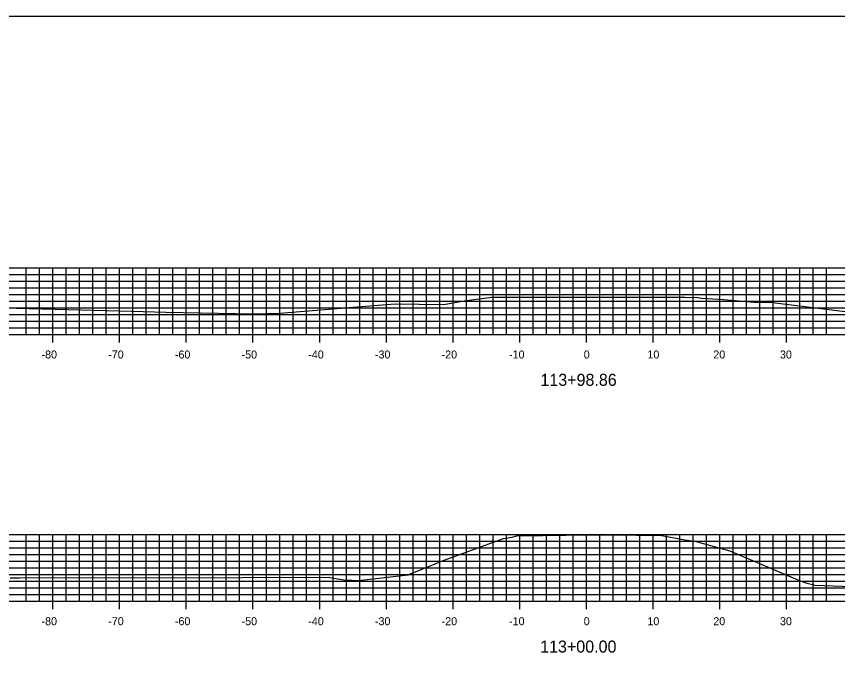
# Model space of a CAD drawing. Extents: x 1661012 to 1662122, y 670053 to 671852.
# Drawn here: x 1661506.5 to 1661629.7, y 671369.5 to 671466.8 of the extents above; entities that cross this region are included whole.
import ezdxf

# ---------------------------------------------------------------- set-up
doc = ezdxf.new("R2010")
doc.units = 0
for name, color, linetype in [('R_Concrete', 7, 'Continuous'), ('R_Concrete Hidden', 7, 'Continuous'), ('R_Erosion', 7, 'Continuous'), ('R_Exist Surface', 7, 'Continuous'), ('R_Proposed Road', 7, 'Continuous')]:
    doc.layers.add(name, color=color, linetype=linetype)

msp = doc.modelspace()

# ---------------------------------------------------------------- linework, layer by layer
at = {"layer": 'R_Concrete'}
for p, q in [((1661441.99, 671429.12), (1661741.99, 671429.12)), ((1661507.99, 671419.12), (1661507.99, 671429.12)), ((1661509.99, 671419.12), (1661509.99, 671429.12)), ((1661511.99, 671419.12), (1661511.99, 671429.12)), ((1661513.99, 671419.12), (1661513.99, 671429.12)), ((1661515.99, 671419.12), (1661515.99, 671429.12)), ((1661517.99, 671419.12), (1661517.99, 671429.12)), ((1661519.99, 671419.12), (1661519.99, 671429.12)), ((1661521.99, 671419.12), (1661521.99, 671429.12)), ((1661523.99, 671419.12), (1661523.99, 671429.12)), ((1661525.99, 671419.12), (1661525.99, 671429.12)), ((1661527.99, 671419.12), (1661527.99, 671429.12)), ((1661529.99, 671419.12), (1661529.99, 671429.12)), ((1661531.99, 671419.12), (1661531.99, 671429.12)), ((1661533.99, 671419.12), (1661533.99, 671429.12)), ((1661535.99, 671419.12), (1661535.99, 671429.12)), ((1661537.99, 671419.12), (1661537.99, 671429.12)), ((1661539.99, 671419.12), (1661539.99, 671429.12)), ((1661541.99, 671419.12), (1661541.99, 671429.12)), ((1661543.99, 671419.12), (1661543.99, 671429.12)), ((1661545.99, 671419.12), (1661545.99, 671429.12)), ((1661547.99, 671419.12), (1661547.99, 671429.12)), ((1661549.99, 671419.12), (1661549.99, 671429.12)), ((1661551.99, 671419.12), (1661551.99, 671429.12)), ((1661553.99, 671419.12), (1661553.99, 671429.12)), ((1661555.99, 671419.12), (1661555.99, 671429.12)), ((1661557.99, 671419.12), (1661557.99, 671429.12)), ((1661559.99, 671419.12), (1661559.99, 671429.12)), ((1661561.99, 671419.12), (1661561.99, 671429.12)), ((1661563.99, 671419.12), (1661563.99, 671429.12)), ((1661565.99, 671419.12), (1661565.99, 671429.12)), ((1661567.99, 671419.12), (1661567.99, 671429.12)), ((1661569.99, 671419.12), (1661569.99, 671429.12)), ((1661571.99, 671419.12), (1661571.99, 671429.12)), ((1661573.99, 671419.12), (1661573.99, 671429.12)), ((1661575.99, 671419.12), (1661575.99, 671429.12)), ((1661577.99, 671419.12), (1661577.99, 671429.12)), ((1661579.99, 671419.12), (1661579.99, 671429.12)), ((1661581.99, 671419.12), (1661581.99, 671429.12)), ((1661583.99, 671419.12), (1661583.99, 671429.12)), ((1661585.99, 671419.12), (1661585.99, 671429.12)), ((1661587.99, 671419.12), (1661587.99, 671429.12)), ((1661589.99, 671419.12), (1661589.99, 671429.12)), ((1661591.99, 671419.12), (1661591.99, 671429.12)), ((1661593.99, 671419.12), (1661593.99, 671429.12)), ((1661595.99, 671419.12), (1661595.99, 671429.12)), ((1661597.99, 671419.12), (1661597.99, 671429.12)), ((1661599.99, 671419.12), (1661599.99, 671429.12)), ((1661601.99, 671419.12), (1661601.99, 671429.12)), ((1661603.99, 671419.12), (1661603.99, 671429.12)), ((1661605.99, 671419.12), (1661605.99, 671429.12)), ((1661607.99, 671419.12), (1661607.99, 671429.12)), ((1661609.99, 671419.12), (1661609.99, 671429.12)), ((1661611.99, 671419.12), (1661611.99, 671429.12)), ((1661613.99, 671419.12), (1661613.99, 671429.12)), ((1661615.99, 671419.12), (1661615.99, 671429.12)), ((1661617.99, 671419.12), (1661617.99, 671429.12)), ((1661619.99, 671419.12), (1661619.99, 671429.12)), ((1661621.99, 671419.12), (1661621.99, 671429.12)), ((1661623.99, 671419.12), (1661623.99, 671429.12)), ((1661625.99, 671419.12), (1661625.99, 671429.12)), ((1661627.99, 671419.12), (1661627.99, 671429.12)), ((1661441.99, 671428.12), (1661741.99, 671428.12)), ((1661441.99, 671427.12), (1661741.99, 671427.12)), ((1661441.99, 671426.12), (1661741.99, 671426.12)), ((1661441.99, 671425.12), (1661741.99, 671425.12)), ((1661441.99, 671424.12), (1661741.99, 671424.12)), ((1661441.99, 671423.12), (1661741.99, 671423.12)), ((1661441.99, 671422.12), (1661741.99, 671422.12)), ((1661441.99, 671421.12), (1661741.99, 671421.12)), ((1661441.99, 671420.12), (1661741.99, 671420.12)), ((1661507.99, 671419.12), (1661507.99, 671419.72)), ((1661509.99, 671419.12), (1661509.99, 671419.72)), ((1661511.99, 671417.92), (1661511.99, 671420.32)), ((1661513.99, 671419.12), (1661513.99, 671419.72)), ((1661515.99, 671419.12), (1661515.99, 671419.72)), ((1661517.99, 671419.12), (1661517.99, 671419.72)), ((1661519.99, 671419.12), (1661519.99, 671419.72)), ((1661521.99, 671417.92), (1661521.99, 671420.32)), ((1661523.99, 671419.12), (1661523.99, 671419.72)), ((1661525.99, 671419.12), (1661525.99, 671419.72)), ((1661527.99, 671419.12), (1661527.99, 671419.72)), ((1661529.99, 671419.12), (1661529.99, 671419.72)), ((1661531.99, 671417.92), (1661531.99, 671420.32)), ((1661533.99, 671419.12), (1661533.99, 671419.72)), ((1661535.99, 671419.12), (1661535.99, 671419.72)), ((1661537.99, 671419.12), (1661537.99, 671419.72)), ((1661539.99, 671419.12), (1661539.99, 671419.72)), ((1661541.99, 671417.92), (1661541.99, 671420.32)), ((1661543.99, 671419.12), (1661543.99, 671419.72)), ((1661545.99, 671419.12), (1661545.99, 671419.72)), ((1661547.99, 671419.12), (1661547.99, 671419.72)), ((1661549.99, 671419.12), (1661549.99, 671419.72)), ((1661551.99, 671417.92), (1661551.99, 671420.32)), ((1661553.99, 671419.12), (1661553.99, 671419.72)), ((1661555.99, 671419.12), (1661555.99, 671419.72)), ((1661557.99, 671419.12), (1661557.99, 671419.72)), ((1661559.99, 671419.12), (1661559.99, 671419.72)), ((1661561.99, 671417.92), (1661561.99, 671420.32)), ((1661563.99, 671419.12), (1661563.99, 671419.72)), ((1661565.99, 671419.12), (1661565.99, 671419.72)), ((1661567.99, 671419.12), (1661567.99, 671419.72)), ((1661569.99, 671419.12), (1661569.99, 671419.72)), ((1661571.99, 671417.92), (1661571.99, 671420.32)), ((1661573.99, 671419.12), (1661573.99, 671419.72)), ((1661575.99, 671419.12), (1661575.99, 671419.72)), ((1661577.99, 671419.12), (1661577.99, 671419.72)), ((1661579.99, 671419.12), (1661579.99, 671419.72)), ((1661581.99, 671417.92), (1661581.99, 671420.32)), ((1661583.99, 671419.12), (1661583.99, 671419.72)), ((1661585.99, 671419.12), (1661585.99, 671419.72)), ((1661587.99, 671419.12), (1661587.99, 671419.72)), ((1661589.99, 671419.12), (1661589.99, 671419.72)), ((1661591.99, 671417.92), (1661591.99, 671420.32)), ((1661593.99, 671419.12), (1661593.99, 671419.72)), ((1661595.99, 671419.12), (1661595.99, 671419.72)), ((1661597.99, 671419.12), (1661597.99, 671419.72)), ((1661599.99, 671419.12), (1661599.99, 671419.72)), ((1661601.99, 671417.92), (1661601.99, 671420.32)), ((1661603.99, 671419.12), (1661603.99, 671419.72)), ((1661605.99, 671419.12), (1661605.99, 671419.72)), ((1661607.99, 671419.12), (1661607.99, 671419.72)), ((1661609.99, 671419.12), (1661609.99, 671419.72)), ((1661611.99, 671417.92), (1661611.99, 671420.32)), ((1661613.99, 671419.12), (1661613.99, 671419.72)), ((1661615.99, 671419.12), (1661615.99, 671419.72)), ((1661617.99, 671419.12), (1661617.99, 671419.72)), ((1661619.99, 671419.12), (1661619.99, 671419.72)), ((1661621.99, 671417.92), (1661621.99, 671420.32)), ((1661623.99, 671419.12), (1661623.99, 671419.72)), ((1661625.99, 671419.12), (1661625.99, 671419.72)), ((1661627.99, 671419.12), (1661627.99, 671419.72)), ((1661441.99, 671419.12), (1661741.99, 671419.12)), ((1661441.99, 671389.12), (1661741.99, 671389.12)), ((1661507.99, 671379.12), (1661507.99, 671389.12)), ((1661509.99, 671379.12), (1661509.99, 671389.12)), ((1661511.99, 671379.12), (1661511.99, 671389.12)), ((1661513.99, 671379.12), (1661513.99, 671389.12)), ((1661515.99, 671379.12), (1661515.99, 671389.12)), ((1661517.99, 671379.12), (1661517.99, 671389.12)), ((1661519.99, 671379.12), (1661519.99, 671389.12)), ((1661521.99, 671379.12), (1661521.99, 671389.12)), ((1661523.99, 671379.12), (1661523.99, 671389.12)), ((1661525.99, 671379.12), (1661525.99, 671389.12)), ((1661527.99, 671379.12), (1661527.99, 671389.12)), ((1661529.99, 671379.12), (1661529.99, 671389.12)), ((1661531.99, 671379.12), (1661531.99, 671389.12)), ((1661533.99, 671379.12), (1661533.99, 671389.12)), ((1661535.99, 671379.12), (1661535.99, 671389.12)), ((1661537.99, 671379.12), (1661537.99, 671389.12)), ((1661539.99, 671379.12), (1661539.99, 671389.12)), ((1661541.99, 671379.12), (1661541.99, 671389.12)), ((1661543.99, 671379.12), (1661543.99, 671389.12)), ((1661545.99, 671379.12), (1661545.99, 671389.12)), ((1661547.99, 671379.12), (1661547.99, 671389.12)), ((1661549.99, 671379.12), (1661549.99, 671389.12)), ((1661551.99, 671379.12), (1661551.99, 671389.12)), ((1661553.99, 671379.12), (1661553.99, 671389.12)), ((1661555.99, 671379.12), (1661555.99, 671389.12)), ((1661557.99, 671379.12), (1661557.99, 671389.12)), ((1661559.99, 671379.12), (1661559.99, 671389.12)), ((1661561.99, 671379.12), (1661561.99, 671389.12)), ((1661563.99, 671379.12), (1661563.99, 671389.12)), ((1661565.99, 671379.12), (1661565.99, 671389.12)), ((1661567.99, 671379.12), (1661567.99, 671389.12)), ((1661569.99, 671379.12), (1661569.99, 671389.12)), ((1661571.99, 671379.12), (1661571.99, 671389.12)), ((1661573.99, 671379.12), (1661573.99, 671389.12)), ((1661575.99, 671379.12), (1661575.99, 671389.12)), ((1661577.99, 671379.12), (1661577.99, 671389.12)), ((1661579.99, 671379.12), (1661579.99, 671389.12)), ((1661581.99, 671379.12), (1661581.99, 671389.12)), ((1661583.99, 671379.12), (1661583.99, 671389.12)), ((1661585.99, 671379.12), (1661585.99, 671389.12)), ((1661587.99, 671379.12), (1661587.99, 671389.12)), ((1661589.99, 671379.12), (1661589.99, 671389.12)), ((1661591.99, 671379.12), (1661591.99, 671389.12)), ((1661593.99, 671379.12), (1661593.99, 671389.12)), ((1661595.99, 671379.12), (1661595.99, 671389.12)), ((1661597.99, 671379.12), (1661597.99, 671389.12)), ((1661599.99, 671379.12), (1661599.99, 671389.12)), ((1661601.99, 671379.12), (1661601.99, 671389.12)), ((1661603.99, 671379.12), (1661603.99, 671389.12)), ((1661605.99, 671379.12), (1661605.99, 671389.12)), ((1661607.99, 671379.12), (1661607.99, 671389.12)), ((1661609.99, 671379.12), (1661609.99, 671389.12)), ((1661611.99, 671379.12), (1661611.99, 671389.12)), ((1661613.99, 671379.12), (1661613.99, 671389.12)), ((1661615.99, 671379.12), (1661615.99, 671389.12)), ((1661617.99, 671379.12), (1661617.99, 671389.12)), ((1661619.99, 671379.12), (1661619.99, 671389.12)), ((1661621.99, 671379.12), (1661621.99, 671389.12)), ((1661623.99, 671379.12), (1661623.99, 671389.12)), ((1661625.99, 671379.12), (1661625.99, 671389.12)), ((1661627.99, 671379.12), (1661627.99, 671389.12)), ((1661441.99, 671388.12), (1661741.99, 671388.12)), ((1661441.99, 671387.12), (1661741.99, 671387.12)), ((1661441.99, 671386.12), (1661741.99, 671386.12)), ((1661441.99, 671385.12), (1661741.99, 671385.12)), ((1661441.99, 671384.12), (1661741.99, 671384.12)), ((1661441.99, 671383.12), (1661741.99, 671383.12)), ((1661441.99, 671382.12), (1661741.99, 671382.12)), ((1661441.99, 671381.12), (1661741.99, 671381.12)), ((1661511.99, 671377.92), (1661511.99, 671380.32)), ((1661521.99, 671377.92), (1661521.99, 671380.32)), ((1661531.99, 671377.92), (1661531.99, 671380.32)), ((1661541.99, 671377.92), (1661541.99, 671380.32)), ((1661551.99, 671377.92), (1661551.99, 671380.32)), ((1661561.99, 671377.92), (1661561.99, 671380.32)), ((1661571.99, 671377.92), (1661571.99, 671380.32)), ((1661581.99, 671377.92), (1661581.99, 671380.32)), ((1661591.99, 671377.92), (1661591.99, 671380.32)), ((1661601.99, 671377.92), (1661601.99, 671380.32)), ((1661611.99, 671377.92), (1661611.99, 671380.32)), ((1661621.99, 671377.92), (1661621.99, 671380.32)), ((1661441.99, 671380.12), (1661741.99, 671380.12)), ((1661441.99, 671379.12), (1661741.99, 671379.12)), ((1661507.99, 671379.12), (1661507.99, 671379.72)), ((1661509.99, 671379.12), (1661509.99, 671379.72)), ((1661513.99, 671379.12), (1661513.99, 671379.72)), ((1661515.99, 671379.12), (1661515.99, 671379.72)), ((1661517.99, 671379.12), (1661517.99, 671379.72)), ((1661519.99, 671379.12), (1661519.99, 671379.72)), ((1661523.99, 671379.12), (1661523.99, 671379.72)), ((1661525.99, 671379.12), (1661525.99, 671379.72)), ((1661527.99, 671379.12), (1661527.99, 671379.72)), ((1661529.99, 671379.12), (1661529.99, 671379.72)), ((1661533.99, 671379.12), (1661533.99, 671379.72)), ((1661535.99, 671379.12), (1661535.99, 671379.72)), ((1661537.99, 671379.12), (1661537.99, 671379.72)), ((1661539.99, 671379.12), (1661539.99, 671379.72)), ((1661543.99, 671379.12), (1661543.99, 671379.72)), ((1661545.99, 671379.12), (1661545.99, 671379.72)), ((1661547.99, 671379.12), (1661547.99, 671379.72)), ((1661549.99, 671379.12), (1661549.99, 671379.72)), ((1661553.99, 671379.12), (1661553.99, 671379.72)), ((1661555.99, 671379.12), (1661555.99, 671379.72)), ((1661557.99, 671379.12), (1661557.99, 671379.72)), ((1661559.99, 671379.12), (1661559.99, 671379.72)), ((1661563.99, 671379.12), (1661563.99, 671379.72)), ((1661565.99, 671379.12), (1661565.99, 671379.72)), ((1661567.99, 671379.12), (1661567.99, 671379.72)), ((1661569.99, 671379.12), (1661569.99, 671379.72)), ((1661573.99, 671379.12), (1661573.99, 671379.72)), ((1661575.99, 671379.12), (1661575.99, 671379.72)), ((1661577.99, 671379.12), (1661577.99, 671379.72)), ((1661579.99, 671379.12), (1661579.99, 671379.72)), ((1661583.99, 671379.12), (1661583.99, 671379.72)), ((1661585.99, 671379.12), (1661585.99, 671379.72)), ((1661587.99, 671379.12), (1661587.99, 671379.72)), ((1661589.99, 671379.12), (1661589.99, 671379.72)), ((1661593.99, 671379.12), (1661593.99, 671379.72)), ((1661595.99, 671379.12), (1661595.99, 671379.72)), ((1661597.99, 671379.12), (1661597.99, 671379.72)), ((1661599.99, 671379.12), (1661599.99, 671379.72)), ((1661603.99, 671379.12), (1661603.99, 671379.72)), ((1661605.99, 671379.12), (1661605.99, 671379.72)), ((1661607.99, 671379.12), (1661607.99, 671379.72)), ((1661609.99, 671379.12), (1661609.99, 671379.72)), ((1661613.99, 671379.12), (1661613.99, 671379.72)), ((1661615.99, 671379.12), (1661615.99, 671379.72)), ((1661617.99, 671379.12), (1661617.99, 671379.72)), ((1661619.99, 671379.12), (1661619.99, 671379.72)), ((1661623.99, 671379.12), (1661623.99, 671379.72)), ((1661625.99, 671379.12), (1661625.99, 671379.72)), ((1661627.99, 671379.12), (1661627.99, 671379.72))]:
    msp.add_line(p, q, dxfattribs=at)
at = {"layer": 'R_Erosion'}
for points in [[(1661500.62, 671423.22), (1661522.02, 671422.65), (1661525.54, 671422.56), (1661528.93, 671422.47), (1661541.99, 671422.2), (1661545.99, 671422.31), (1661558.86, 671423.35), (1661563.29, 671423.71), (1661570.49, 671423.63), (1661570.88, 671423.69), (1661573.98, 671424.23), (1661577.45, 671424.66), (1661577.45, 671424.66), (1661577.47, 671424.67), (1661577.77, 671424.74), (1661590.88, 671424.71), (1661591.86, 671424.7), (1661592.61, 671424.71), (1661593.07, 671424.72), (1661593.74, 671424.72), (1661606.81, 671424.72), (1661607.52, 671424.66), (1661608.41, 671424.7), (1661609.24, 671424.55), (1661612.59, 671424.35), (1661617.16, 671423.99), (1661619.89, 671423.93), (1661642.07, 671421.19)], [(1661505.56, 671382.63), (1661506.98, 671382.62), (1661540.37, 671382.69), (1661553.3, 671382.71), (1661553.53, 671382.66), (1661555.91, 671382.27), (1661556.79, 671382.26), (1661557.82, 671382.25), (1661562.15, 671382.71), (1661565.28, 671383.1), (1661565.38, 671383.14), (1661570.64, 671385.28), (1661579.58, 671388.53), (1661580.84, 671388.75), (1661581.69, 671388.95), (1661585.44, 671388.97), (1661592.38, 671389.09), (1661599.5, 671389.02), (1661603.02, 671389), (1661606.76, 671388.34), (1661608.47, 671388.06), (1661609.16, 671387.89), (1661613.51, 671386.68), (1661624.04, 671382.16), (1661624.87, 671381.88), (1661626.28, 671381.51), (1661631.76, 671381.33)]]:
    msp.add_lwpolyline(points, dxfattribs=at)
at = {"layer": 'R_Exist Surface'}
for p, q in [((1661441.99, 671419.12), (1661741.99, 671419.12)), ((1661441.99, 671379.12), (1661741.99, 671379.12))]:
    msp.add_line(p, q, dxfattribs=at)
at = {"layer": 'R_Proposed Road'}
msp.add_lwpolyline([(1661411.99, 671274.12), (1661771.99, 671274.12), (1661771.99, 671466.82), (1661411.99, 671466.82)], close=True, dxfattribs=at)

# ---------------------------------------------------------------- texts
at = {"layer": 'R_Concrete Hidden'}
for s, height, p in [('-80', 1.2, (1661510.28, 671415.52)), ('-70', 1.2, (1661520.28, 671415.52)), ('-60', 1.2, (1661530.28, 671415.52)), ('-50', 1.2, (1661540.28, 671415.52)), ('-40', 1.2, (1661550.28, 671415.52)), ('-30', 1.2, (1661560.28, 671415.52)), ('-20', 1.2, (1661570.28, 671415.52)), ('-10', 1.2, (1661580.39, 671415.52)), ('0', 1.2, (1661591.59, 671415.52)), ('10', 1.2, (1661601.14, 671415.52)), ('20', 1.2, (1661611.02, 671415.52)), ('30', 1.2, (1661621.02, 671415.52)), ('113+98.86', 1.8, (1661585.09, 671411.42)), ('-80', 1.2, (1661510.28, 671375.52)), ('-70', 1.2, (1661520.28, 671375.52)), ('-60', 1.2, (1661530.28, 671375.52)), ('-50', 1.2, (1661540.28, 671375.52)), ('-40', 1.2, (1661550.28, 671375.52)), ('-30', 1.2, (1661560.28, 671375.52)), ('-20', 1.2, (1661570.28, 671375.52)), ('-10', 1.2, (1661580.39, 671375.52)), ('0', 1.2, (1661591.59, 671375.52)), ('10', 1.2, (1661601.14, 671375.52)), ('20', 1.2, (1661611.02, 671375.52)), ('30', 1.2, (1661621.02, 671375.52)), ('113+00.00', 1.8, (1661585.05, 671371.42))]:
    msp.add_text(s, height=height, dxfattribs=at).set_placement(p)

doc.saveas('drawing.dxf')
